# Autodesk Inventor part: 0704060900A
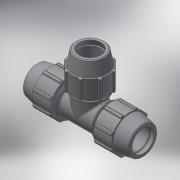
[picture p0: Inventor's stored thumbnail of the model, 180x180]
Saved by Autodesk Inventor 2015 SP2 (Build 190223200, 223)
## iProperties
Created: 2017-02
Part Number: 0704060900A
Material: Generic
Description: PLASSON TEE 90-90-90
Document SubType Name: Modeling
Designer: KIM
Mass: 2642.84 g
Surface Area: 3396.39 cm^2
Volume: 2642.84 cm^3
Density: 1 g/cm^3
Appearance: Default
Author: KIM
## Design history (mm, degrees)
derived "87040.ipt"
feature "Solid1::87040.ipt"
tag "TaggingFeature1"
body "Solid1"
other parameters: "d4" = 18.33333, "d5" = 55, "d7" = 154, "d13" = 120 deg, "d14" = 117, "d15" = 10 deg, "d18" = 4.5, "d19" = 35 deg, "d20" = 17.5 deg, "d21" = 143.22, "d23" = 0, "d25" = 360 deg, "d27" = 3.08, "d42" = 77, "d43" = 4.62, "d46" = 2.7, "d63" = 165, "d67" = 115.5, "d77" = 154, "d78" = 10 deg, "d80" = 120 deg, "d81" = 117, "d82" = 18.33333, "d85" = 115.5, "d87" = 7.33333, "d88" = 7.33333, "d89" = 55, "d90" = 77, "d98" = 143.22, "d99" = 35 deg, "d100" = 17.5 deg, "d102" = 0, "d103" = 3.08, "d107" = 360 deg, "d109" = 2.7, "d112" = 4.5, "d118" = 360 deg, "d121" = 0, "d128" = 439, "d131" = 81, "d132" = 81, "d133" = 165, "d134" = 3.3, "d152" = 0, "d154" = 0, "d156" = 0, "d158" = 0, "d163" = 16.5, "d165" = 18.15, "d166" = 109.725, "d167" = 109.725, "d168" = 6.05, "d169" = 127.05, "d170" = 3.025, "d171" = 4.5375, "d172" = 127.05, "d173" = 5.5, "d174" = 2.75, "d175" = 4.125, "d176" = 1.8, "d177" = 4.5, "E_" = 154, "l_" = 165, "H_" = 439, "d162" = 33, "d164" = 36.3
